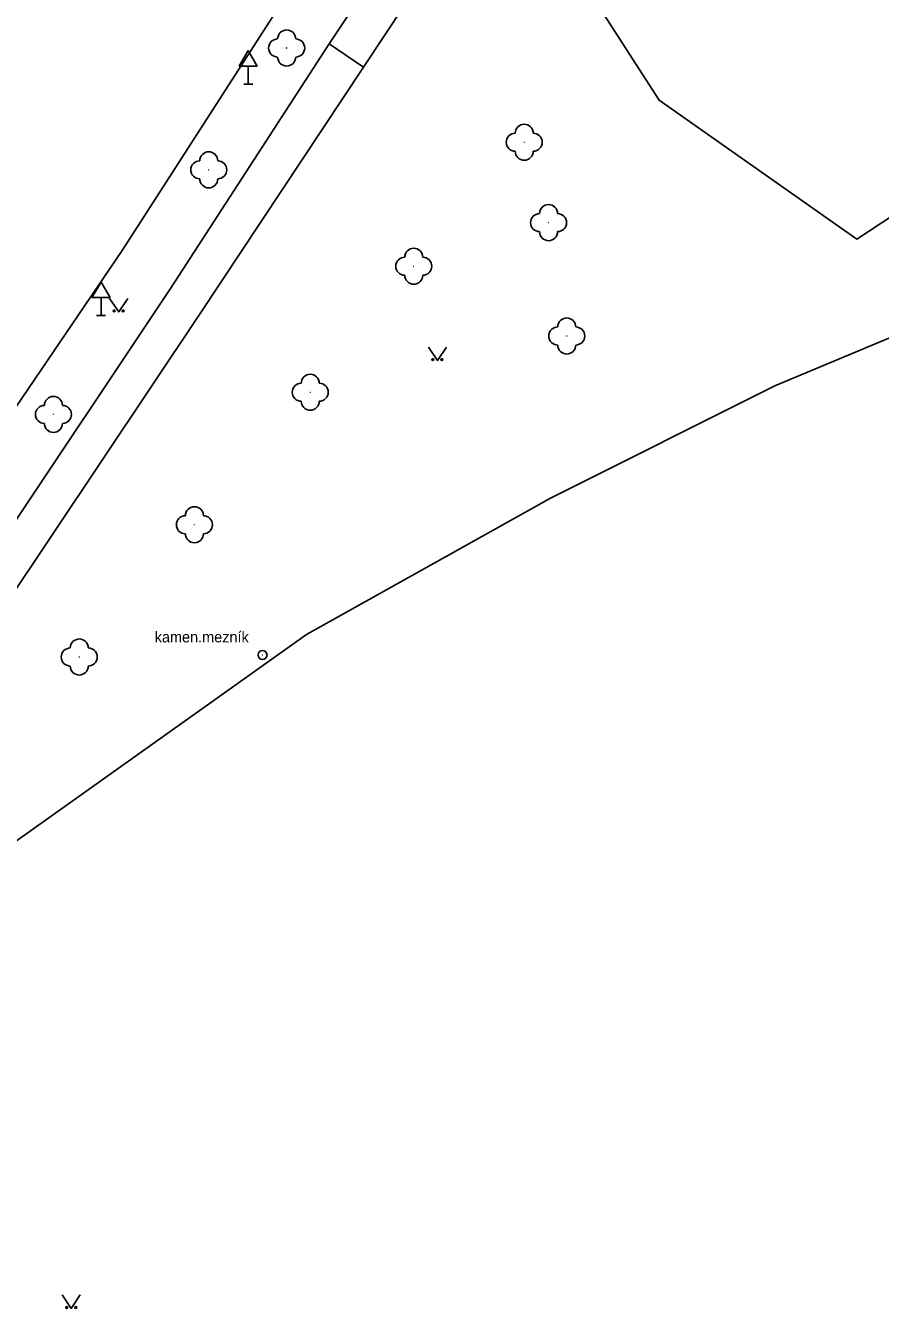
# Model space of a CAD drawing. Extents: x -794191 to -788944, y -1117087 to -1105044.
# Drawn here: x -792370.1 to -792322.7, y -1110130.1 to -1110058.9 of the extents above; entities that cross this region are included whole.
import ezdxf

# ---------------------------------------------------------------- set-up
doc = ezdxf.new("R2010")
doc.units = 0
for name, color, linetype in [('Doplněk polohopisu', 7, 'Continuous'), ('Doplňkové značky', 7, 'Continuous'), ('Hranice - ploty_ zdi', 7, 'Continuous'), ('Komunikace', 7, 'Continuous'), ('temporary_level_1', 7, 'Continuous'), ('Výškopis', 7, 'Continuous'), ('Zeleň', 7, 'Continuous'), ('Značky druhů pozemků', 7, 'Continuous')]:
    doc.layers.add(name, color=color, linetype=linetype)

msp = doc.modelspace()

# ---------------------------------------------------------------- linework, layer by layer
at = {"layer": 'Doplněk polohopisu'}
for p, q in [((-792353.29, -1110059.92), (-792362.09, -1110073.5)), ((-792351.38, -1110061.22), (-792353.29, -1110059.92)), ((-792360.44, -1110074.89), (-792351.38, -1110061.22)), ((-792362.09, -1110073.5), (-792373.97, -1110091.32)), ((-792371.35, -1110091.23), (-792360.44, -1110074.89))]:
    msp.add_line(p, q, dxfattribs=at)
for points in [[(-792338.33, -1110035.73), (-792344.13, -1110046.18), (-792353.29, -1110059.92)], [(-792351.38, -1110061.22), (-792342.21, -1110047.37), (-792336.54, -1110037.22)]]:
    msp.add_lwpolyline(points, dxfattribs=at)
at = {"layer": 'Doplňkové značky'}
for p, q in [((-792357.77, -1110060.294), (-792358.27, -1110061.16)), ((-792357.77, -1110060.294), (-792357.27, -1110061.16)), ((-792358.27, -1110061.16), (-792357.27, -1110061.16)), ((-792357.77, -1110062.16), (-792357.77, -1110061.16)), ((-792358.02, -1110062.16), (-792357.52, -1110062.16)), ((-792365.94, -1110073.144), (-792366.44, -1110074.01)), ((-792365.94, -1110073.144), (-792365.44, -1110074.01)), ((-792366.44, -1110074.01), (-792365.44, -1110074.01)), ((-792365.94, -1110075.01), (-792365.94, -1110074.01)), ((-792366.19, -1110075.01), (-792365.69, -1110075.01))]:
    msp.add_line(p, q, dxfattribs=at)
at = {"layer": 'Hranice - ploty_ zdi'}
msp.add_line((-792354.54, -1110092.7), (-792375.15, -1110107.37), dxfattribs=at)
msp.add_lwpolyline([(-792312.19, -1110072.07), (-792328.56, -1110078.91), (-792341, -1110085.14), (-792354.54, -1110092.7)], dxfattribs=at)
at = {"layer": 'Komunikace'}
msp.add_line((-792374.82, -1110086.18), (-792364.77, -1110071.4), dxfattribs=at)
msp.add_lwpolyline([(-792364.77, -1110071.4), (-792353.47, -1110053.82), (-792348.75, -1110046.44)], dxfattribs=at)
at = {"layer": 'temporary_level_1'}
for radius in [0.25, 0.0005]:
    msp.add_circle((-792356.98, -1110093.84), radius, dxfattribs=at)
at = {"layer": 'Výškopis'}
msp.add_lwpolyline([(-792334.73, -1110046.65), (-792338.64, -1110057.36), (-792334.98, -1110063.06), (-792324, -1110070.76), (-792317.31, -1110066.37), (-792313.89, -1110066.27), (-792312.19, -1110072.07)], dxfattribs=at)
at = {"layer": 'Zeleň'}
for centre in [(-792355.64, -1110060.16), (-792342.46, -1110065.39), (-792359.96, -1110066.92), (-792341.11, -1110069.85), (-792348.59, -1110072.27), (-792340.1, -1110076.14), (-792354.33, -1110079.26), (-792368.58, -1110080.49), (-792360.76, -1110086.61), (-792367.15, -1110093.95)]:
    msp.add_circle(centre, 0.0005, dxfattribs=at)
for centre, start, end in [((-792356.14, -1110060.16), 89.99999, 269.99999), ((-792355.64, -1110059.66), 0, 179.99999), ((-792355.14, -1110060.16), 270, 89.99999), ((-792355.64, -1110060.66), 179.99999, 359.99999), ((-792342.46, -1110064.89), 0, 179.99999), ((-792342.96, -1110065.39), 89.99999, 269.99999), ((-792341.96, -1110065.39), 270, 89.99999), ((-792359.96, -1110066.42), 0, 179.99999), ((-792342.46, -1110065.89), 179.99999, 359.99999), ((-792360.46, -1110066.92), 89.99999, 269.99999), ((-792359.46, -1110066.92), 270, 89.99999), ((-792359.96, -1110067.42), 179.99999, 359.99999), ((-792341.11, -1110069.35), 0, 179.99999), ((-792341.61, -1110069.85), 89.99999, 269.99999), ((-792340.61, -1110069.85), 270, 89.99999), ((-792341.11, -1110070.35), 179.99999, 359.99999), ((-792349.09, -1110072.27), 89.99999, 269.99999), ((-792348.59, -1110071.77), 0, 179.99999), ((-792348.09, -1110072.27), 270, 89.99999), ((-792348.59, -1110072.77), 179.99999, 359.99999), ((-792340.1, -1110075.64), 0, 179.99999), ((-792340.6, -1110076.14), 89.99999, 269.99999), ((-792339.6, -1110076.14), 270, 89.99999), ((-792340.1, -1110076.64), 179.99999, 359.99999), ((-792354.33, -1110078.76), 0, 179.99999), ((-792354.83, -1110079.26), 89.99999, 269.99999), ((-792353.83, -1110079.26), 270, 89.99999), ((-792368.58, -1110079.99), 0, 179.99999), ((-792354.33, -1110079.76), 179.99999, 359.99999), ((-792369.08, -1110080.49), 89.99999, 269.99999), ((-792368.08, -1110080.49), 270, 89.99999), ((-792368.58, -1110080.99), 179.99999, 359.99999), ((-792361.26, -1110086.61), 89.99999, 269.99999), ((-792360.76, -1110086.11), 0, 179.99999), ((-792360.26, -1110086.61), 270, 89.99999), ((-792360.76, -1110087.11), 179.99999, 359.99999), ((-792367.15, -1110093.45), 0, 179.99999), ((-792367.65, -1110093.95), 89.99999, 269.99999), ((-792366.65, -1110093.95), 270, 89.99999), ((-792367.15, -1110094.45), 179.99999, 359.99999)]:
    msp.add_arc(centre, 0.5, start, end, dxfattribs=at)
at = {"layer": 'Značky druhů pozemků'}
for points in [[(-792365.46, -1110074.05), (-792364.96, -1110074.8), (-792364.46, -1110074.05)], [(-792347.78, -1110076.75), (-792347.28, -1110077.5), (-792346.78, -1110076.75)], [(-792368.09, -1110129.34), (-792367.59, -1110130.09), (-792367.09, -1110129.34)]]:
    msp.add_lwpolyline(points, dxfattribs=at)
for centre in [(-792365.21, -1110074.75), (-792364.71, -1110074.75), (-792347.53, -1110077.45), (-792347.03, -1110077.45), (-792367.84, -1110130.04), (-792367.34, -1110130.04)]:
    msp.add_circle(centre, 0.05, dxfattribs=at)

# ---------------------------------------------------------------- texts
at = {"layer": 'temporary_level_1'}
msp.add_text('kamen.mezník', height=0.6, dxfattribs=at).set_placement((-792362.96, -1110093.14))

doc.saveas('drawing.dxf')
